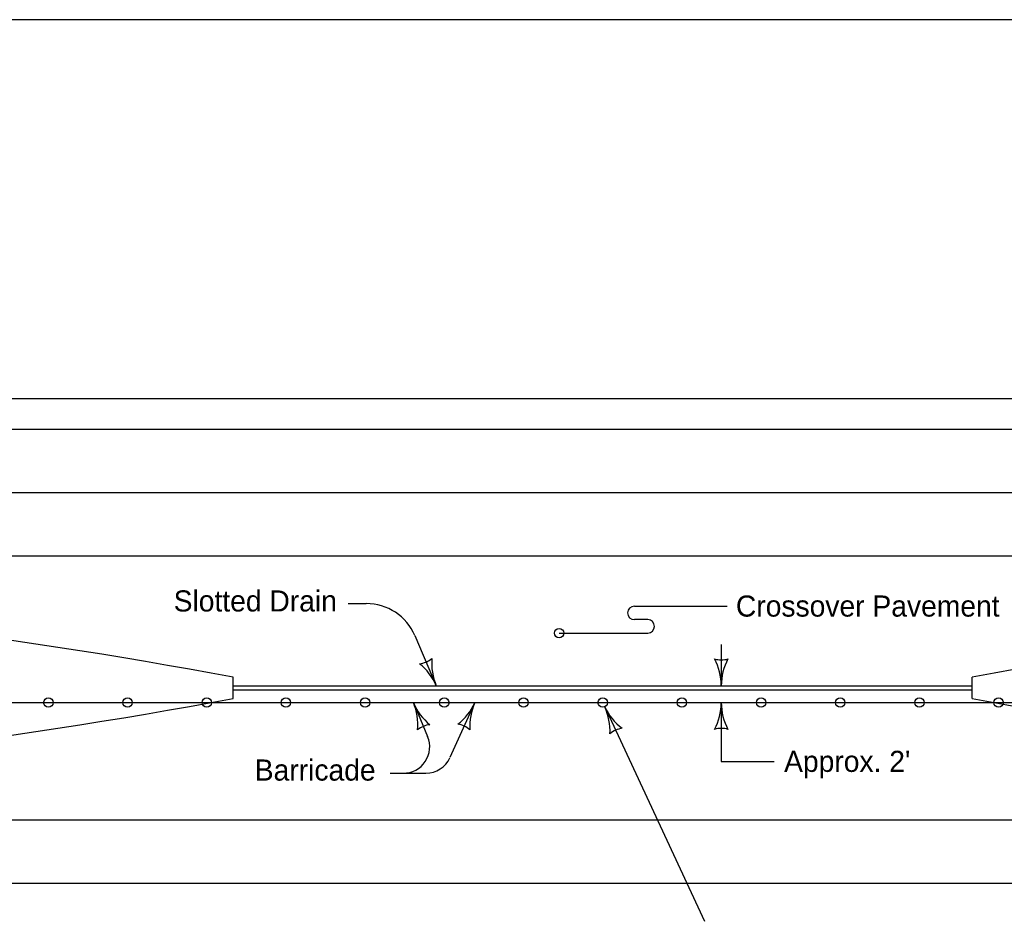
# Model space of a CAD drawing. Extents: x 228 to 3572, y -1307 to 1277.
# Drawn here: x 956 to 1702, y 594 to 1277 of the extents above; entities that cross this region are included whole.
import ezdxf

# ---------------------------------------------------------------- set-up
doc = ezdxf.new("R2010")
doc.units = 0
for name, color, linetype in [('dsnShtPlotShapeBatchPrint', 7, 'Continuous'), ('dsnStdBorder', 7, 'Continuous'), ('dsnStdDimension', 7, 'Continuous'), ('Level 2', 7, 'Continuous')]:
    doc.layers.add(name, color=color, linetype=linetype)

msp = doc.modelspace()

# ---------------------------------------------------------------- linework, layer by layer
at = {"layer": 'dsnShtPlotShapeBatchPrint'}
msp.add_lwpolyline([(227.98, -1306.99), (3571.98, -1306.99), (3571.98, 1277.01), (227.98, 1277.01)], close=True, dxfattribs=at)
at = {"layer": 'dsnStdBorder'}
msp.add_lwpolyline([(332.48, 990.01), (3467.48, 990.01), (3467.48, -1019.99), (332.48, -1019.99)], close=True, dxfattribs=at)
at = {"layer": 'dsnStdDimension'}
for p, q in [((1421.85, 832.53), (1492.11, 832.53)), ((1432.01, 822.37), (1421.85, 822.37)), ((1255.52, 810.28), (1271.78, 772.31)), ((1364.83, 812.21), (1432.01, 812.21)), ((1487.72, 803.61), (1487.72, 772.31)), ((1254.45, 759.51), (1265.25, 733.73)), ((1301.01, 759.51), (1282.17, 717.78)), ((1399.36, 756.29), (1475.11, 593.77)), ((1487.72, 759.51), (1487.72, 714.86)), ((1487.72, 714.86), (1527.71, 714.86)), ((1236.86, 706), (1263.94, 706))]:
    msp.add_line(p, q, dxfattribs=at)
msp.add_circle((1364.83, 812.21), 3.56, dxfattribs=at)
for centre, radius, start, end in [((1218.75, 794.53), 40, 23.18478, 90), ((1421.85, 827.45), 5.08, 90, 270), ((1432, 817.29), 5.08, 270, 90), ((1257.53, 805.6), 16.68, 275.44927, 310.91598), ((1311.47, 789.31), 43.18, 175.11014, 203.18263), ((1487.72, 808.52), 16.68, 252.26665, 287.73335), ((1444.54, 772.31), 43.18, 0, 28.07249), ((1530.89, 772.31), 43.18, 151.92751, 180), ((1232.09, 755.31), 43.18, 23.18263, 51.25511), ((1294.28, 776.19), 43.18, 202.72171, 230.7942), ((1214.62, 742.83), 43.18, 354.64922, 22.72171), ((1261.65, 777.27), 43.18, 307.64283, 335.71532), ((1340.36, 741.75), 43.18, 155.71532, 183.78781), ((1438.5, 774.53), 43.18, 204.98887, 233.06136), ((1360.23, 738.05), 43.18, 356.91638, 24.98887), ((1444.54, 759.51), 43.18, 331.92751, 0), ((1530.89, 759.51), 43.18, 180, 208.07249), ((1268.44, 726.12), 16.68, 94.98836, 130.45506), ((1286.12, 726.51), 16.68, 47.98196, 83.44867), ((1414.66, 723.47), 16.68, 97.25551, 132.72222), ((1487.72, 723.31), 16.68, 72.26665, 107.73335), ((1246.8, 726), 20, 270, 22.72202), ((1263.94, 726), 20, 270, 335.71271)]:
    msp.add_arc(centre, radius, start, end, dxfattribs=at)
at = {"layer": 'Level 2'}
for p, q in [((519.47, 966.71), (2276.26, 966.71)), ((519.47, 918.71), (2276.26, 918.71)), ((519.47, 870.71), (2276.26, 870.71)), ((1205.13, 834.53), (1218.75, 834.53)), ((1117.87, 762.71), (1117.87, 778.71)), ((1677.86, 762.71), (1677.86, 778.71)), ((1117.87, 772.31), (1677.86, 772.31)), ((1117.87, 769.11), (1677.86, 769.11)), ((805.87, 759.51), (1989.86, 759.51)), ((519.47, 670.71), (2276.26, 670.71)), ((519.47, 622.71), (2276.26, 622.71))]:
    msp.add_line(p, q, dxfattribs=at)
for centre in [(977.86, 759.51), (1037.86, 759.51), (1097.86, 759.51), (1157.86, 759.51), (1217.86, 759.51), (1277.86, 759.51), (1337.86, 759.51), (1397.86, 759.51), (1457.86, 759.51), (1517.86, 759.51), (1577.86, 759.51), (1637.86, 759.51), (1697.86, 759.51)]:
    msp.add_circle(centre, 3.56, dxfattribs=at)
for centre, start, end in [((367.46, -3224.72), 79.38365, 86.96007), ((2428.27, -3224.72), 93.03998, 100.61635), ((367.46, 4766.14), 273.03993, 280.61635), ((2428.27, 4766.14), 259.38365, 266.96002)]:
    msp.add_arc(centre, 4073.15, start, end, dxfattribs=at)

# ---------------------------------------------------------------- texts
at = {"layer": 'dsnStdDimension'}
for s, p in [('Slotted Drain', (1072.8, 828.54)), ('Crossover Pavement', (1498.8, 824.67)), ('Barricade', (1134.25, 700.39)), ("Approx. 2'", (1535.31, 706.98))]:
    msp.add_text(s, height=16, dxfattribs=at).set_placement(p)

doc.saveas('drawing.dxf')
